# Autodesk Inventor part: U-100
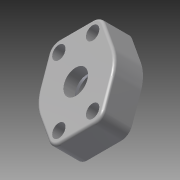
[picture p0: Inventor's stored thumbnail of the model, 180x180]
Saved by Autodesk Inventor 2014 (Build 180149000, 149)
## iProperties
Created: 2011-01
Part Number: U-100
Material: Steel
Document SubType Name: Modeling
Designer: deckm
Density: 7.85 g/cm^3
Description: FLARED FLANGE SAE WITH CLEARANCE HOLES
Mass: 259.498 g
Surface Area: 100.719 cm^2
Volume: 33.0571 cm^3
Appearance: Steel
Author: deckm
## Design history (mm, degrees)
derived "union_cap.ipt"
body "Solid1"
feature "Solid1::union_cap.ipt"
tag "TaggingFeature1"
other parameters: "d1" = 70.104, "d3" = 19.10263, "d25" = 26.162, "FilletTop" = 2, "d27" = 12.7, "d28" = 37 deg, "d29" = 22.098, "d30" = 9.525, "FilletCorners" = 8.89, "FilletEnds" = 29.337, "d8" = 22.098, "d9" = 0, "d12" = 10.31875, "d21" = 26.162, "d24" = 52.324
